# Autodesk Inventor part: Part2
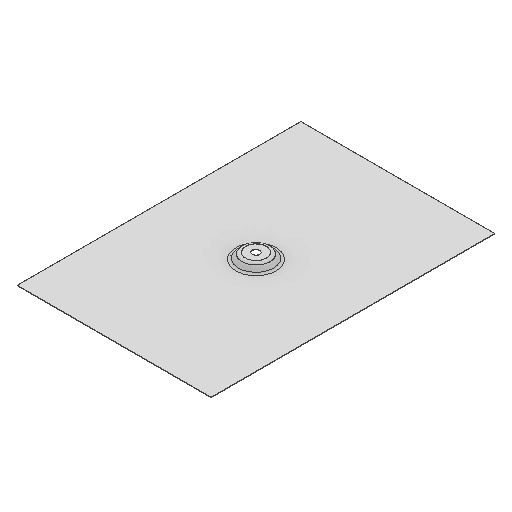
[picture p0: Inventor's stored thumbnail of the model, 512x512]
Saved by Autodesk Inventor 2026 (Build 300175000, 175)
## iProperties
Created: 2025-03
Part Number: Part2
Material: Generic
Document SubType Name: Sheet Metal
Designer: zhangy5
Density: 1 g/cm^3
Sheet Metal Rule: Default_mm
Appearance: Default
Author: zhangy5
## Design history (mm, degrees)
node "Face1"
  sketch "Sketch1"
    geometry: L1 (99.185, 145.092)-(-99.185, 145.092); L2 (-99.185, 145.092)-(-99.185, -145.092); L3 (-99.185, -145.092)-(99.185, -145.092); L4 (99.185, -145.092)-(99.185, 145.092); L5 (99.185, 145.092)-(-99.185, -145.092); L6 (-99.185, 145.092)-(99.185, -145.092); 1 further point
    constraints: 12 end point, 2 midpoint, 2 parallel, 1 horizontal, 1 perpendicular
sketch "Sketch2"
  geometry: L1 (-12.7, 0)-(12.7, 0); L2 (0, -12.7)-(0, 12.7); C1 r 3.81 at (0, 0); A1 r 12.7 centre (0, 0) between (-12.7, 0) and (12.7, 0); 2 further points
  constraints: 4 end point, 4 point on circle, 3 coincident, 2 centre point, 1 horizontal, 1 vertical
  dimensions: "Diameter" = 25.4 diameter of A1; "Inner_Diameter" = 7.62 diameter of C1
extrude "Extrusion1" join sketch "Sketch2" taper "d3" = 0 deg; distance "Height" = 6.35
workplane "Work Plane1"
sketch "Sketch4"
  geometry: C1 r 12.7 at (0, 0)
  constraints: 1 centre point
  dimensions: "d6" = 25.4 diameter of C1 (= Diameter)
extrude "Extrusion2" join sketch "Sketch4" distance "d7" = 6.35 (= Height); taper "Angle" = 45 deg
sketch "Sketch3"
  geometry: C1 r 12.7 at (0, 0)
  constraints: 1 centre point
  dimensions: "d5" = 25.4 diameter of C1 (= Diameter)
extrude "Extrusion3" cut sketch "Sketch3" distance "d9" = 6.35 (= Height); taper "d10" = 45 deg (= Angle)
extrude "Extrusion5" cut sketch "Sketch2" stored distance "d21" = 10; taper "d22" = 0 deg
fillet "Fillet1" dims "d14" = 3.81, "d23" = 5.08 (= Top_Fillet), "Top_Fillet" = 5.08
sketch "Sketch6"
  geometry: C1 r 12.7 at (0, 0); C2 r 3.81 at (0, 0); 3 further points
  constraints: 4 coincident, 2 centre point
  dimensions: "d18" = 25.4 diameter of C1 (= Diameter); "d19" = 7.62 diameter of C2 (= Top_Diameter)
body "Solid1"
face "Plate1" dims "d0" = 0.5 (= Thickness)
other parameters: "Thickness" = 0.5 (derived), "BendRadius" = 0.5 (= Thickness), "BendReliefWidth" = 0.5 (= Thickness), "BendReliefDepth" = 0.25 (= 0.5 x Thickness), "CornerReliefSize" = 2 (= 4 x Thickness), "SeamGap" = 0.00508, "MinimumRemnant" = 1 (= 2 x Thickness), "TransitionRadius" = 0.5 (= BendRadius), "JacobiRadiusSize" = 0.5 (= BendRadius), "GapSize" = 0.5 (= Thickness), "d4" = -0.5 (= -Thickness), "Top_Diameter" = 7.62
